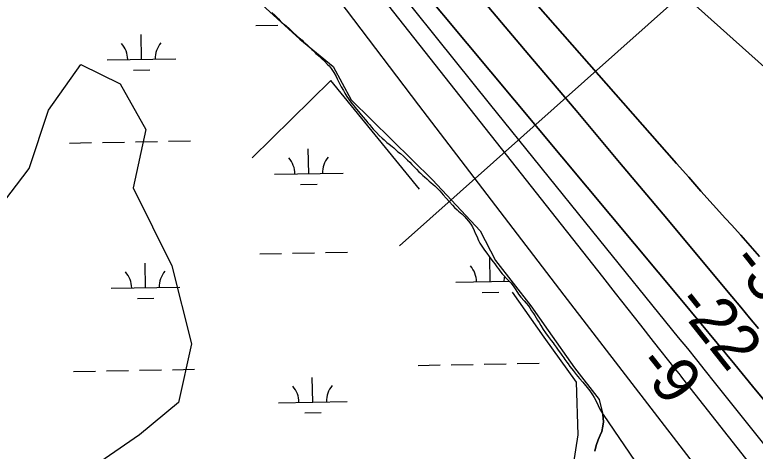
# Model space of a CAD drawing. Extents: x 3903937 to 3942190, y 260677 to 286651.
# Drawn here: x 3925742 to 3926819, y 273792 to 274427 of the extents above; entities that cross this region are included whole.
import ezdxf

# ---------------------------------------------------------------- set-up
doc = ezdxf.new("R2010")
doc.units = 0
for name, color, linetype in [('V-RIVR-EDGE', 7, 'Continuous'), ('V-RIVR-RANG', 7, 'Continuous'), ('V-RRAP-FSHR', 7, 'Continuous'), ('V-SITE-VEGE', 7, 'Continuous'), ('V-TOPO-DPTH', 7, 'Continuous'), ('V-TOPO-MAJR', 7, 'Continuous'), ('V-TOPO-MINR', 7, 'Continuous'), ('V-TOPO-SHOR', 7, 'Continuous'), ('V-UTIL-LINE', 7, 'Continuous'), ('V-WETL-SWMP', 7, 'Continuous')]:
    doc.layers.add(name, color=color, linetype=linetype)

msp = doc.modelspace()

# ---------------------------------------------------------------- linework, layer by layer
at = {"layer": 'V-RIVR-EDGE'}
msp.add_line((3926598, 273845.5), (3926791.4, 273563.5), dxfattribs=at)
msp.add_lwpolyline([(3925056.9, 275630.2), (3925314.1, 275376.2), (3925378.1, 275316.4), (3925470.4, 275209.4), (3925555.5, 275119.1), (3925641.5, 275028.8), (3925721.3, 274922.8), (3925794.7, 274824.2), (3925865.1, 274722.4), (3925978.4, 274588), (3926090.7, 274452.6), (3926156.8, 274391.8), (3926205.1, 274351.9), (3926231.4, 274303.6), (3926349.9, 274187.1), (3926419.2, 274112.6), (3926441.3, 274069.6), (3926492.7, 274003.4), (3926517.9, 273967.8), (3926556.7, 273913.2), (3926592.4, 273867), (3926597.9, 273845.3)], dxfattribs=at)
at = {"layer": 'V-RRAP-FSHR'}
for points in [[(3926330.9, 274173.3), (3926201.9, 274331.5), (3926144.7, 274275.4), (3926087.5, 274219.3)], [(3926465.8, 274023.2), (3926511.9, 273957.8), (3926558.8, 273892.5), (3926561.3, 273815.6), (3926549.3, 273737.3), (3926490.3, 273684.2), (3926428.6, 273633), (3926367.1, 273581.7), (3926305.7, 273530.5)]]:
    msp.add_lwpolyline(points, dxfattribs=at)
at = {"layer": 'V-SITE-VEGE'}
msp.add_lwpolyline([(3925762.5, 274203.6), (3925790.8, 274288.7), (3925838.1, 274355), (3925894.9, 274326.6), (3925932.7, 274260.3), (3925913.8, 274175.2), (3925942.1, 274118.4), (3925970.5, 274061.6), (3925998.9, 273948.1), (3925980, 273862.9), (3925923.2, 273815.6), (3925771.9, 273711.5), (3925658.4, 273654.8), (3925554.4, 273664.2), (3925526, 273721), (3925535.5, 273796.7), (3925497.7, 273796.7), (3925384.2, 273825.1), (3925393.6, 273872.4), (3925422, 273929.2), (3925507.1, 273948.1), (3925611.1, 274004.9)], close=True, dxfattribs=at)
at = {"layer": 'V-TOPO-DPTH'}
for points in [[(3926824.1, 273970.5), (3926811.3, 273986.1), (3926798.4, 274001.7), (3926785.5, 274017.2), (3926685.3, 274137.1), (3926622.1, 274212.5), (3926558.9, 274287.8), (3926495.4, 274362.9), (3926431.9, 274438), (3926049.4, 274889.2), (3926031.4, 274910.5), (3926013.3, 274931.8), (3925995.3, 274953.2), (3925977.3, 274974.5), (3925959.3, 274995.8), (3925941.1, 275017), (3925922.9, 275038.1), (3925904.5, 275059.1), (3925586.2, 275421.6), (3925570.5, 275439.4), (3925554.7, 275457.2), (3925538.8, 275474.9), (3925522.9, 275492.5), (3925400.1, 275628)], [(3926824.1, 273970.5), (3926811.3, 273986.1), (3926798.4, 274001.7), (3926785.5, 274017.2), (3926685.3, 274137.1), (3926622.1, 274212.5), (3926558.9, 274287.8), (3926495.4, 274362.9), (3926431.9, 274438), (3926049.4, 274889.2), (3926031.4, 274910.5), (3926013.3, 274931.8), (3925995.3, 274953.2), (3925977.3, 274974.5), (3925959.3, 274995.8), (3925941.1, 275017), (3925922.9, 275038.1), (3925904.5, 275059.1), (3925586.2, 275421.6), (3925570.5, 275439.4), (3925554.7, 275457.2), (3925538.8, 275474.9), (3925522.9, 275492.5), (3925400.1, 275628)], [(3925637, 275435.8), (3926014.8, 275001.6), (3926032.6, 274981), (3926050.5, 274960.5), (3926068.4, 274939.8), (3926086.2, 274919.2), (3926175.3, 274816.2), (3926237.7, 274744.1), (3926300.3, 274672.2), (3926363, 274600.4), (3926425.8, 274528.6), (3926705, 274210.8), (3926722.7, 274190.7), (3926740.5, 274170.6), (3926758.4, 274150.7), (3926776.3, 274130.8), (3926784.8, 274121.4), (3926798.5, 274106.2), (3926812.2, 274090.9), (3926825.8, 274075.6)], [(3926825.8, 274075.6), (3926812.2, 274090.9), (3926798.5, 274106.2), (3926784.8, 274121.4), (3926776.3, 274130.8), (3926758.4, 274150.7), (3926740.5, 274170.6), (3926722.7, 274190.7), (3926705, 274210.8), (3926425.8, 274528.6), (3926363, 274600.4), (3926300.3, 274672.2), (3926237.7, 274744.1), (3926175.3, 274816.2), (3926086.2, 274919.2), (3926068.4, 274939.8), (3926050.5, 274960.5), (3926032.6, 274981), (3926014.8, 275001.6), (3925637, 275435.8)], [(3926834.3, 273863.5), (3926815.5, 273886.6), (3926790, 273917.9), (3926764.3, 273949.1), (3926738.6, 273980.2), (3926712.8, 274011.2), (3926400.3, 274385.5), (3926329.1, 274471.3), (3926258.1, 274557.4), (3926187.6, 274643.8), (3926117.4, 274730.5), (3926001.1, 274874.8), (3925989.3, 274889.5), (3925977.4, 274904.2), (3925965.6, 274918.9), (3925953.8, 274933.6), (3925833.2, 275083.6), (3925784.6, 275143.1), (3925735.4, 275202)], [(3925735.4, 275202), (3925784.6, 275143.1), (3925833.2, 275083.6), (3925953.8, 274933.6), (3925965.6, 274918.9), (3925977.4, 274904.2), (3925989.3, 274889.5), (3926001.1, 274874.8), (3926117.4, 274730.5), (3926187.6, 274643.8), (3926258.1, 274557.4), (3926329.1, 274471.3), (3926400.3, 274385.5), (3926712.8, 274011.2), (3926738.6, 273980.2), (3926764.3, 273949.1), (3926790, 273917.9), (3926815.5, 273886.6), (3926834.3, 273863.5)], [(3925719.2, 275149.5), (3925772.3, 275085.9), (3925824.7, 275021.9), (3925931, 274890.3), (3925936.4, 274883.6), (3925941.8, 274876.8), (3925947.2, 274870), (3925952.6, 274863.2), (3926597, 274045.7), (3926615.5, 274022.2), (3926634, 273998.7), (3926652.6, 273975.2), (3926671.1, 273951.8), (3926702.6, 273911.9), (3926705.4, 273908.4), (3926708.2, 273904.8), (3926711, 273901.3), (3926713.8, 273897.7), (3926956.1, 273589.6)]]:
    msp.add_lwpolyline(points, dxfattribs=at)
at = {"layer": 'V-TOPO-MAJR'}
msp.add_lwpolyline([(3925589.3, 275587), (3925610.7, 275564.3), (3925631.8, 275541.4), (3925652.5, 275518.2), (3925673, 275494.7), (3925880.2, 275253.9), (3925917.4, 275211.6), (3925955.2, 275169.8), (3925993.9, 275128.8), (3926033.1, 275088.3), (3926065.1, 275056), (3926088.9, 275032.1), (3926112.6, 275008.3), (3926136.4, 274984.5), (3926160.3, 274960.8), (3926235, 274886.6), (3926933.5, 274261.2)], dxfattribs=at)
at = {"layer": 'V-TOPO-MINR'}
for points in [[(3925400.1, 275628), (3925522.9, 275492.5), (3925538.8, 275474.9), (3925554.7, 275457.2), (3925570.5, 275439.4), (3925586.2, 275421.6), (3925904.5, 275059.1), (3925922.9, 275038.1), (3925941.1, 275017), (3925959.3, 274995.8), (3925977.3, 274974.5), (3925995.3, 274953.2), (3926013.3, 274931.8), (3926031.4, 274910.5), (3926049.4, 274889.2), (3926431.9, 274438), (3926495.4, 274362.9), (3926558.9, 274287.8), (3926622.1, 274212.5), (3926685.3, 274137.1), (3926785.5, 274017.2), (3926798.4, 274001.7), (3926811.3, 273986.1), (3926824.1, 273970.5)], [(3925637, 275435.8), (3926014.8, 275001.6), (3926032.6, 274981), (3926050.5, 274960.5), (3926068.4, 274939.8), (3926086.2, 274919.2), (3926175.3, 274816.2), (3926237.7, 274744.1), (3926300.3, 274672.2), (3926363, 274600.4), (3926425.8, 274528.6), (3926705, 274210.8), (3926722.7, 274190.7), (3926740.5, 274170.6), (3926758.4, 274150.7), (3926776.3, 274130.8), (3926784.8, 274121.4), (3926798.5, 274106.2), (3926812.2, 274090.9), (3926825.8, 274075.6)], [(3925393.9, 275427.9), (3925454.7, 275367.3), (3925459.3, 275362.6), (3925463.8, 275358), (3925468.3, 275353.3), (3925472.7, 275348.5), (3925643.7, 275162.6), (3925689.4, 275112), (3925734.6, 275061), (3925779, 275009.3), (3925822.8, 274957.1), (3925860.8, 274911.2), (3925885, 274881.4), (3925909, 274851.5), (3925932.5, 274821.2), (3925955.8, 274790.7), (3926119.1, 274573.7), (3926224.1, 274434.6), (3926329.3, 274295.9), (3926435, 274157.4), (3926541, 274019.2), (3927114, 273274.5)], [(3925619.6, 275316.4), (3925921.6, 274937.6), (3925940.5, 274914), (3925959.3, 274890.3), (3925978.2, 274866.6), (3925997.1, 274842.9), (3926282.2, 274485.7), (3926357.1, 274392), (3926432.2, 274298.4), (3926507.5, 274205), (3926582.9, 274111.6), (3926707.6, 273957.5), (3926720.8, 273941.3), (3926733.9, 273925.1), (3926746.9, 273908.8), (3926760, 273892.5), (3927064.3, 273511.1)], [(3925735.4, 275202), (3925784.6, 275143.1), (3925833.2, 275083.6), (3925953.8, 274933.6), (3925965.6, 274918.9), (3925977.4, 274904.2), (3925989.3, 274889.5), (3926001.1, 274874.8), (3926117.4, 274730.5), (3926187.6, 274643.8), (3926258.1, 274557.4), (3926329.1, 274471.3), (3926400.3, 274385.5), (3926712.8, 274011.2), (3926738.6, 273980.2), (3926764.3, 273949.1), (3926790, 273917.9), (3926815.5, 273886.6), (3926834.3, 273863.5)], [(3925719.2, 275149.5), (3925772.3, 275085.9), (3925824.7, 275021.9), (3925931, 274890.3), (3925936.4, 274883.6), (3925941.8, 274876.8), (3925947.2, 274870), (3925952.6, 274863.2), (3926597, 274045.7), (3926615.5, 274022.2), (3926634, 273998.7), (3926652.6, 273975.2), (3926671.1, 273951.8), (3926702.6, 273911.9), (3926705.4, 273908.4), (3926708.2, 273904.8), (3926711, 273901.3), (3926713.8, 273897.7), (3926956.1, 273589.6)]]:
    msp.add_lwpolyline(points, dxfattribs=at)
at = {"layer": 'V-TOPO-SHOR'}
msp.add_lwpolyline([(3926586.3, 273791.8), (3926587.8, 273800.3), (3926590.7, 273808.6), (3926594, 273815.1), (3926596.3, 273820.7), (3926597.8, 273828.2), (3926598.5, 273834.8), (3926597.9, 273845.3)], dxfattribs=at)
at = {"layer": 'V-UTIL-LINE'}
msp.add_line((3928669.1, 276200), (3926301.7, 274090.8), dxfattribs=at)
at = {"layer": 'V-WETL-SWMP'}
for p, q in [((3926116, 274430.5), (3926120.2, 274426.6)), ((3926120.2, 274426.6), (3926125.4, 274421.6)), ((3926092.4, 274411.9), (3926124.4, 274412.5)), ((3926125.4, 274421.6), (3926128.2, 274418.6)), ((3926128.2, 274418.6), (3926131.5, 274415.3)), ((3926131.5, 274415.3), (3926134.1, 274413.1)), ((3926134.1, 274413.1), (3926137.1, 274411)), ((3926137.1, 274411), (3926140.5, 274407.9)), ((3926140.5, 274407.9), (3926146.5, 274402.2)), ((3926146.5, 274402.2), (3926152.5, 274396.9)), ((3925926.1, 274362.6), (3925925.5, 274398.6)), ((3926152.5, 274396.9), (3926155.8, 274394)), ((3926155.8, 274394), (3926159.8, 274390.3)), ((3926159.8, 274390.3), (3926162.2, 274388.1)), ((3926162.2, 274388.1), (3926166.7, 274383.9)), ((3926166.7, 274383.9), (3926170.2, 274380.6)), ((3926170.2, 274380.6), (3926173.9, 274377)), ((3926173.9, 274377), (3926176.3, 274374.7)), ((3926176.3, 274374.7), (3926180.1, 274371.2)), ((3926180.1, 274371.2), (3926182.4, 274369)), ((3926182.4, 274369), (3926188.1, 274363.7)), ((3925876.1, 274361.7), (3925976.1, 274363.4)), ((3926188.1, 274363.7), (3926193, 274359.3)), ((3926193, 274359.3), (3926197.1, 274355.2)), ((3925914.4, 274346.9), (3925938.4, 274347.3)), ((3926197.1, 274355.2), (3926199.3, 274352.8)), ((3926199.3, 274352.8), (3926202.3, 274349.2)), ((3926202.3, 274349.2), (3926206.2, 274343.3)), ((3926206.2, 274343.3), (3926209.3, 274337.6)), ((3926209.3, 274337.6), (3926210.9, 274334.1)), ((3926210.9, 274334.1), (3926213.8, 274328.3)), ((3926213.8, 274328.3), (3926216.8, 274322.6)), ((3926216.8, 274322.6), (3926220.1, 274316.9)), ((3926220.1, 274316.9), (3926222.1, 274313.2)), ((3926222.1, 274313.2), (3926225, 274308.5)), ((3926225, 274308.5), (3926227.5, 274304.9)), ((3926227.5, 274304.9), (3926229.3, 274302.1)), ((3926229.3, 274302.1), (3926232.8, 274297.9)), ((3926232.8, 274297.9), (3926235.2, 274294.7)), ((3926235.2, 274294.7), (3926239.3, 274289.7)), ((3926239.3, 274289.7), (3926242, 274286.3)), ((3926242, 274286.3), (3926246.1, 274281.5)), ((3926246.1, 274281.5), (3926248.8, 274278.3)), ((3926248.8, 274278.3), (3926252.4, 274274.2)), ((3926252.4, 274274.2), (3926255.8, 274270.1)), ((3926255.8, 274270.1), (3926258, 274267.5)), ((3926258, 274267.5), (3926261.2, 274263.5)), ((3926261.2, 274263.5), (3926263.4, 274261)), ((3926263.4, 274261), (3926268.4, 274255.9)), ((3926268.4, 274255.9), (3926272.2, 274251.8)), ((3926272.2, 274251.8), (3926276.6, 274247.7)), ((3925821.4, 274240.6), (3925853.4, 274241.2)), ((3925869.4, 274241.5), (3925901.4, 274242)), ((3925917.4, 274242.3), (3925949.4, 274242.9)), ((3925965.4, 274243.2), (3925997.4, 274243.7)), ((3926276.6, 274247.7), (3926279.3, 274245.4)), ((3926279.3, 274245.4), (3926283.5, 274241.4)), ((3926283.5, 274241.4), (3926286.5, 274238.8)), ((3926286.5, 274238.8), (3926291, 274235.6)), ((3926169.6, 274196), (3926168.9, 274232)), ((3926291, 274235.6), (3926293.6, 274233.8)), ((3926293.6, 274233.8), (3926296.3, 274230.9)), ((3926296.3, 274230.9), (3926299.3, 274227.9)), ((3926299.3, 274227.9), (3926303.2, 274225.2)), ((3926303.2, 274225.2), (3926307.5, 274221.4)), ((3926307.5, 274221.4), (3926313.2, 274215.9)), ((3926313.2, 274215.9), (3926316.6, 274212.6)), ((3926316.6, 274212.6), (3926319.7, 274209.5)), ((3926319.7, 274209.5), (3926323.9, 274205.1)), ((3926119.6, 274195.1), (3926219.6, 274196.9)), ((3926323.9, 274205.1), (3926326.3, 274202.6)), ((3926326.3, 274202.6), (3926329.7, 274198.9)), ((3926329.7, 274198.9), (3926332.3, 274196.8)), ((3926332.3, 274196.8), (3926335.9, 274193.4)), ((3926335.9, 274193.4), (3926338.3, 274191.3)), ((3926338.3, 274191.3), (3926341.7, 274188.3)), ((3926341.7, 274188.3), (3926345.1, 274185.2)), ((3926345.1, 274185.2), (3926347.4, 274183.1)), ((3926157.8, 274180.4), (3926181.8, 274180.8)), ((3926347.4, 274183.1), (3926350.8, 274180.2)), ((3926350.8, 274180.2), (3926353.1, 274178.1)), ((3926353.1, 274178.1), (3926357.4, 274174)), ((3926357.4, 274174), (3926360.5, 274170.8)), ((3926360.5, 274170.8), (3926365.4, 274165.4)), ((3926365.4, 274165.4), (3926369.8, 274160.2)), ((3926369.8, 274160.2), (3926374.3, 274155.2)), ((3926374.3, 274155.2), (3926378.8, 274149.9)), ((3926378.8, 274149.9), (3926382, 274146.7)), ((3926382, 274146.7), (3926385.6, 274143.4)), ((3926385.6, 274143.4), (3926387.8, 274141.2)), ((3926387.8, 274141.2), (3926392.3, 274137.4)), ((3926392.3, 274137.4), (3926396.8, 274133)), ((3926396.8, 274133), (3926399, 274130.5)), ((3926399, 274130.5), (3926402.3, 274126.8)), ((3926402.3, 274126.8), (3926405.6, 274122.7)), ((3926405.6, 274122.7), (3926408.2, 274118.4)), ((3926408.2, 274118.4), (3926410.6, 274113.2)), ((3926410.6, 274113.2), (3926412.1, 274109.5)), ((3926412.1, 274109.5), (3926414.2, 274104.8)), ((3926414.2, 274104.8), (3926416.8, 274098.9)), ((3926416.8, 274098.9), (3926418.8, 274094.8)), ((3926418.8, 274094.8), (3926420.5, 274092.1)), ((3926420.5, 274092.1), (3926423.5, 274087.6)), ((3926098.2, 274079.3), (3926130.2, 274079.9)), ((3926146.2, 274080.1), (3926178.2, 274080.7)), ((3926194.2, 274081), (3926226.2, 274081.6)), ((3926423.5, 274087.6), (3926425.4, 274084.6)), ((3926425.4, 274084.6), (3926428.7, 274080.1)), ((3926428.7, 274080.1), (3926432.1, 274075.3)), ((3926432.1, 274075.3), (3926434.5, 274072)), ((3926433.8, 274038.8), (3926433.2, 274073.8)), ((3926434.5, 274072), (3926437.9, 274067.4)), ((3926437.9, 274067.4), (3926440.3, 274064.5)), ((3925932, 274029.9), (3925931.4, 274065.9)), ((3926440.3, 274064.5), (3926443.6, 274060.1)), ((3926443.6, 274060.1), (3926445.7, 274057.2)), ((3926445.7, 274057.2), (3926447.9, 274054.4)), ((3926447.9, 274054.4), (3926451, 274050.3)), ((3926451, 274050.3), (3926453.4, 274047.6)), ((3926453.4, 274047.6), (3926457.6, 274043.5)), ((3926383.8, 274037.9), (3926461.5, 274039.3)), ((3926457.6, 274043.5), (3926460.1, 274040.7)), ((3926460.1, 274040.7), (3926463.8, 274036.9)), ((3926463.8, 274036.9), (3926465.8, 274034.5)), ((3926465.8, 274034.5), (3926469.3, 274029.9)), ((3925882, 274029.1), (3925982, 274030.8)), ((3926422.1, 274023.1), (3926446.1, 274023.6)), ((3926469.3, 274029.9), (3926471.3, 274027)), ((3926471.3, 274027), (3926474.8, 274020.7)), ((3925920.3, 274014.3), (3925944.3, 274014.7)), ((3926474.8, 274020.7), (3926478.1, 274016.2)), ((3926478.1, 274016.2), (3926483.3, 274010.6)), ((3926483.3, 274010.6), (3926485.9, 274007.5)), ((3926485.9, 274007.5), (3926489.3, 274003.3)), ((3926489.3, 274003.3), (3926491.4, 274000.5)), ((3926491.4, 274000.5), (3926494.1, 273996.3)), ((3926494.1, 273996.3), (3926497, 273992.2)), ((3926497, 273992.2), (3926498.6, 273989.5)), ((3926498.6, 273989.5), (3926502.7, 273982.6)), ((3926502.7, 273982.6), (3926504.9, 273979.1)), ((3926504.9, 273979.1), (3926507.5, 273974.7)), ((3926507.5, 273974.7), (3926510.7, 273969.3)), ((3926510.7, 273969.3), (3926514.2, 273964.4)), ((3926514.2, 273964.4), (3926518.1, 273958.9)), ((3926518.1, 273958.9), (3926522.6, 273953.2)), ((3926522.6, 273953.2), (3926525.3, 273949.6)), ((3926525.3, 273949.6), (3926527.1, 273947.1)), ((3926527.1, 273947.1), (3926530, 273943.2)), ((3926530, 273943.2), (3926532.9, 273939.2)), ((3926532.9, 273939.2), (3926536.3, 273934.4)), ((3926536.3, 273934.4), (3926538.2, 273931.7)), ((3926538.2, 273931.7), (3926540.8, 273927.9)), ((3926540.8, 273927.9), (3926542.4, 273925.3)), ((3926329.1, 273916.8), (3926361.1, 273917.4)), ((3926377.1, 273917.7), (3926409.1, 273918.2)), ((3926425.1, 273918.5), (3926457.1, 273919.1)), ((3926473.1, 273919.4), (3926505.1, 273919.9)), ((3926542.4, 273925.3), (3926545.2, 273921.6)), ((3926545.2, 273921.6), (3926547, 273919.1)), ((3926547, 273919.1), (3926549.8, 273915.4)), ((3925827.3, 273908), (3925859.3, 273908.6)), ((3925875.3, 273908.9), (3925907.3, 273909.4)), ((3925923.3, 273909.7), (3925955.3, 273910.3)), ((3925971.3, 273910.5), (3926003.2, 273911.1)), ((3926549.8, 273915.4), (3926552.7, 273911.6)), ((3926552.7, 273911.6), (3926554.6, 273909.2)), ((3926554.6, 273909.2), (3926559.1, 273903.5)), ((3926175.4, 273863.4), (3926174.8, 273899.4)), ((3926559.1, 273903.5), (3926563.8, 273897.8)), ((3926563.8, 273897.8), (3926568.4, 273892.2)), ((3926568.4, 273892.2), (3926570.3, 273889.8)), ((3926570.3, 273889.8), (3926574.7, 273884.7)), ((3926574.7, 273884.7), (3926578.8, 273879.8)), ((3926578.8, 273879.8), (3926582.7, 273874)), ((3926582.7, 273874), (3926585.2, 273870.1)), ((3926125.4, 273862.5), (3926225.4, 273864.3)), ((3926585.2, 273870.1), (3926588.3, 273863.5)), ((3926588.3, 273863.5), (3926590.8, 273858.2)), ((3926590.8, 273858.2), (3926593.1, 273853)), ((3926593.1, 273853), (3926595.6, 273849)), ((3926163.7, 273847.7), (3926187.7, 273848.2)), ((3926595.6, 273849), (3926597.9, 273845.3)), ((3926597.9, 273845.3), (3926598.5, 273834.8)), ((3926598.5, 273834.8), (3926597.8, 273828.2)), ((3926596.3, 273820.7), (3926594, 273815.1)), ((3926597.8, 273828.2), (3926596.3, 273820.7)), ((3926590.7, 273808.6), (3926587.8, 273800.3)), ((3926594, 273815.1), (3926590.7, 273808.6)), ((3926587.8, 273800.3), (3926586.3, 273791.8))]:
    msp.add_line(p, q, dxfattribs=at)
for centre, start, end in [((3925870.9, 274362.1), 0.2366, 41.7802), ((3925981.4, 274364), 140.2366, 181.7802), ((3926114.3, 274195.5), 0.2366, 41.7802), ((3926224.8, 274197.5), 140.2366, 181.7802), ((3926378.6, 274038.3), 0.2366, 41.7802), ((3925876.7, 274029.4), 0.2366, 41.7802), ((3925987.2, 274031.4), 140.2366, 181.7802), ((3926489, 274040.2), 169.5246, 181.7802), ((3926120.2, 273862.9), 0.2366, 41.7802), ((3926230.7, 273864.8), 140.2366, 181.7802)]:
    msp.add_arc(centre, 35.2, start, end, dxfattribs=at)

# ---------------------------------------------------------------- texts
at = {"layer": 'V-RIVR-RANG'}
for s, p in [('-39', (3926781.2, 274066.4)), ('-22', (3926701.1, 274006.3)), ('-9', (3926644.4, 273916.9))]:
    msp.add_text(s, height=67, rotation=308.3912, dxfattribs=at).set_placement(p)

doc.saveas('drawing.dxf')
